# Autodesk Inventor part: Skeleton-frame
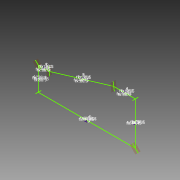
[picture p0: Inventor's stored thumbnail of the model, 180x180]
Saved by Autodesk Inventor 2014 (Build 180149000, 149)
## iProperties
Created: 2009-03
Part Number: Skeleton-frame
Document SubType Name: Modeling
Designer: garding
Density: 1 g/cm^3
Material: Generic
Appearance: Default
FrameW: 1.500 in
FrameH: 3.500 in
d20: 3.000 in
d21: 5.000 in
d30: 3.000 in
d31: 5.000 in
d36: 3.000 in
d37: 5.000 in
d42: 3.000 in
d43: 5.000 in
d48: 3.000 in
d49: 5.000 in
d0: 3772.276 mm
d1: 914.400 mm
d2: 1662.856 mm
d3: 81.69 deg
d5: 81.69 deg
d7: 81.69 deg
d8: 81.69 deg
d9: 304.800 mm
d10: 304.800 mm
d12: 38.100 mm
d13: 88.900 mm
d14: 19.050 mm
d15: 44.450 mm
d16: 38.100 mm
d17: 88.900 mm
d18: 19.050 mm
d19: 44.450 mm
d52: 45.00 deg
d53: 45.00 deg
d26: 38.100 mm
d27: 88.900 mm
d28: 19.050 mm
d29: 44.450 mm
d32: 38.100 mm
d33: 88.900 mm
d34: 19.050 mm
d35: 44.450 mm
d38: 38.100 mm
d39: 88.900 mm
d40: 19.050 mm
d41: 44.450 mm
d44: 38.100 mm
d45: 88.900 mm
d46: 19.050 mm
d47: 44.450 mm
Author: garding
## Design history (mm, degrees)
sketch "Sketch1"
  geometry: L1 (0, 0)-(3772.276, 0); L2 (3772.276, 0)-(3772.276, 1662.856); L3 (3772.276, 1662.856)-(2931.388, 1662.856); L4 (2931.388, 1662.856)-(423.63, 914.4); L5 (423.63, 914.4)-(0, 914.4); L6 (0, 914.4)-(0, 0); L7 (401.606, 1065.2)-(445.654, 763.6); L8 (2909.364, 1813.656)-(2953.411, 1512.056); L9 (3880.039, 1770.619)-(3664.513, 1555.093); L10 (3664.513, 107.763)-(3880.039, -107.763); L11 (-107.763, -107.763)-(107.763, 107.763); L12 (107.763, 806.637)-(-107.763, 1022.163); 6 further points
  constraints: 24 end point, 12 midpoint, 4 equal length, 3 parallel, 3 perpendicular, 1 horizontal
  dimensions: "d0" = 3772.27615 distance of L1.start L1.end (derived); "d1" = 914.4 distance of L5.end L1.start (derived); "d2" = 1662.8558 distance of L1.end L2.end (derived); "d3" = 81.691 deg angle of L5 L7 (derived); "d5" = 81.691 deg angle of L4 L7 (= d3); "d7" = 81.691 deg angle of L3 L8 (= d8); "d8" = 81.691 deg angle of L4 L8 (derived); "d9" = 304.8 distance of L8.start L8.end; "d10" = 304.8 distance of L7.start L7.end (= d9); "d52" = 45 deg angle of L6 L12; "d53" = 45 deg angle of L1 L11 (= d52); "d72" = 840.88832 distance of L2.end L3.end (derived)
workplane "Work Plane1"
workplane "Work Plane2"
workplane "Work Plane3"
workplane "Work Plane4"
workplane "Work Plane5"
workplane "Work Plane6"
sketch "Sketch2"
  geometry: L1 (-19.05, -44.45)-(19.05, -44.45); L2 (19.05, -44.45)-(19.05, 44.45); L3 (19.05, 44.45)-(-19.05, 44.45); L4 (-19.05, 44.45)-(-19.05, -44.45); 2 further points
  constraints: 8 end point, 2 parallel, 1 coincident, 1 horizontal, 1 perpendicular
  dimensions: "d12" = 38.1 distance of L1.start L1.end (= FrameW); "d13" = 88.9 distance of L1.end L2.end (= FrameH); "d14" = 19.05 distance from line of L4 point (0, 0) (= 0.5 x d12); "d15" = 44.45 distance from line of L1 point (0, 0) (= 0.5 x d13)
sketch "Sketch3" dims "d0" = 3772.27615 (derived), "d1" = 914.4 (derived), "d2" = 1662.8558 (derived), "d3" = 81.691 deg (derived), "d5" = 81.691 deg (= d3), "d7" = 81.691 deg (= d8), "d8" = 81.691 deg (derived), "d72" = 840.88832 (derived)
  geometry: L1 (-19.05, -44.45)-(19.05, -44.45); L2 (19.05, -44.45)-(19.05, 44.45); L3 (19.05, 44.45)-(-19.05, 44.45); L4 (-19.05, 44.45)-(-19.05, -44.45); 3 further points
  constraints: 8 end point, 2 coincident, 2 parallel, 1 horizontal, 1 perpendicular
  dimensions: "d16" = 38.1 distance of L1.start L1.end (derived); "d17" = 88.9 distance of L1.end L2.end (derived); "d18" = 19.05 distance from line of L4 point (0, 0) (= 0.5 x d16); "d19" = 44.45 distance from line of L1 point (0, 0) (= 0.5 x d17)
sketch "Sketch4"
  geometry: L1 (-19.05, -44.45)-(19.05, -44.45); L2 (19.05, -44.45)-(19.05, 44.45); L3 (19.05, 44.45)-(-19.05, 44.45); L4 (-19.05, 44.45)-(-19.05, -44.45); 4 further points
  constraints: 8 end point, 3 coincident, 2 parallel, 1 horizontal, 1 perpendicular
  dimensions: "d26" = 38.1 distance of L1.start L1.end (derived); "d27" = 88.9 distance of L1.end L2.end (derived); "d28" = 19.05 distance from line of L4 point (0, 0) (= 0.5 x d26); "d29" = 44.45 distance from line of L1 point (0, 0) (= 0.5 x d27)
sketch "Sketch5"
  geometry: L1 (-19.05, -44.45)-(19.05, -44.45); L2 (19.05, -44.45)-(19.05, 44.45); L3 (19.05, 44.45)-(-19.05, 44.45); L4 (-19.05, 44.45)-(-19.05, -44.45); 4 further points
  constraints: 8 end point, 3 coincident, 2 parallel, 1 horizontal, 1 perpendicular
  dimensions: "d32" = 38.1 distance of L1.start L1.end (derived); "d33" = 88.9 distance of L1.end L2.end (derived); "d34" = 19.05 distance from line of L4 point (0, 0) (= 0.5 x d32); "d35" = 44.45 distance from line of L1 point (0, 0) (= 0.5 x d33)
sketch "Sketch6"
  geometry: L1 (-19.05, -44.45)-(19.05, -44.45); L2 (19.05, -44.45)-(19.05, 44.45); L3 (19.05, 44.45)-(-19.05, 44.45); L4 (-19.05, 44.45)-(-19.05, -44.45); 4 further points
  constraints: 8 end point, 3 coincident, 2 parallel, 1 horizontal, 1 perpendicular
  dimensions: "d38" = 38.1 distance of L1.start L1.end (derived); "d39" = 88.9 distance of L1.end L2.end (derived); "d40" = 19.05 distance from line of L4 point (0, 0) (= 0.5 x d38); "d41" = 44.45 distance from line of L1 point (0, 0) (= 0.5 x d39)
sketch "Sketch7"
  geometry: L1 (-19.05, -44.45)-(19.05, -44.45); L2 (19.05, -44.45)-(19.05, 44.45); L3 (19.05, 44.45)-(-19.05, 44.45); L4 (-19.05, 44.45)-(-19.05, -44.45); 7 further points
  constraints: 8 end point, 6 coincident, 2 parallel, 1 horizontal, 1 perpendicular
  dimensions: "d44" = 38.1 distance of L1.start L1.end (derived); "d45" = 88.9 distance of L1.end L2.end (derived); "d46" = 19.05 distance from line of L4 point (0, 0) (= 0.5 x d44); "d47" = 44.45 distance from line of L1 point (0, 0) (= 0.5 x d45)
sketch "Sketch8"
  geometry: L1 (107.763, 806.637)-(-107.763, 1022.163) reference; L2 (-107.763, -107.763)-(107.763, 107.763) reference; L3 (3664.513, 107.763)-(3880.039, -107.763) reference; L4 (3880.039, 1770.619)-(3664.513, 1555.093) reference; L5 (2909.364, 1813.656)-(2953.411, 1512.056) reference; L6 (401.606, 1065.2)-(445.654, 763.6) reference
extrude_surface "ExtrusionSrf13" dims "d73" = 203.2, "d74" = 0
extrude_surface "ExtrusionSrf14" dims "d75" = 203.2, "d76" = 0
extrude_surface "ExtrusionSrf15" dims "d77" = 203.2, "d78" = 0
extrude_surface "ExtrusionSrf16" dims "d79" = 203.2, "d80" = 0
extrude_surface "ExtrusionSrf17" dims "d81" = 203.2, "d82" = 0
extrude_surface "ExtrusionSrf18" dims "d83" = 203.2, "d84" = 0
body "Srf1"
body "Srf2"
body "Srf3"
body "Srf4"
body "Srf5"
body "Srf6"
other parameters: "FrameW" = 38.1 [user parameter; used in 1 equation term], "FrameH" = 88.9 [user parameter; used in 1 equation term], "d20" = 76.2 [user parameter], "d21" = 127 [user parameter], "d30" = 76.2 [user parameter], "d31" = 127 [user parameter], "d36" = 76.2 [user parameter], "d37" = 127 [user parameter], "d42" = 76.2 [user parameter], "d43" = 127 [user parameter], "d48" = 76.2 [user parameter], "d49" = 127 [user parameter]
